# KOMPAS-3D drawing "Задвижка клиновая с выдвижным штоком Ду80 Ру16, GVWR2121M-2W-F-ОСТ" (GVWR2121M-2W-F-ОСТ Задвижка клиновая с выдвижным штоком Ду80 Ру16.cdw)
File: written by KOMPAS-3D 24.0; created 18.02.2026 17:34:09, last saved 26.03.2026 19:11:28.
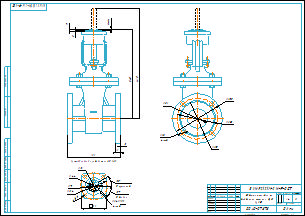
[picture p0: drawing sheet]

Document properties: Автор: R2D2; Форматы листов документа: A2; Полное имя файла: GVWR2121M-2W-F-ОСТ Задвижка клиновая с видвижным штоком Ду80 Ру16.cdw; Масса: 24; Наименование: Задвижка клиновая с выдвижным штоком Ду80 Ру16; Количество листов документа: 1; Примечание: D040-07878

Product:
- Part/product: Задвижка клиновая с выдвижным штоком Ду80 Ру16  | designation GVWR2121M-2W-F-ОСТ
    Масса: 24
    Раздел спецификации: Прочие изделия
    Форматы листов документа: A2
    Примечание: D040-07878

Views: Проекционный вид 2, Проекционный вид 3
Referenced files in E:\Работа\Зайцев\GVWR2121M-2W-F-ОСТ Задвижка клиновая с видвижным штоком Ду50-300 Ру16\DN80\: GVWR2121M-2W-F-ОСТ Задвижка клиновая с видвижным штоком Ду80 Ру16.m3d, GVWR2121M-2W-F-ОСТ Задвижка клиновая с выдвижным штоком Ду80 Ру16.m3d
Referenced files in E:\Работа\Зайцев\Для компаса\: чертеж DN.ru А3.cdt
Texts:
  GVWR2121M-2W-F-ОСТ
  Присоединение привода тип АК (А)
  чертеж DN.ru А3.cdt
  Задвижка клиновая с
  выдвижным штоком Ду80
  Ру16
  Задвижка клиновая с выдвижным штоком Ду80 Ру16
  GVWR2121M-2W-F-ОСТ Задвижка клиновая с выдвижным штоком Ду80 Ру16
Dimensions and other numbers on the sheet: 0; 3; 4; 195; 135; 80; 18; 4 отв.; 160; 100; 5 кулачков; 5 впадин; 14 (М12); 13,5; 104; 70; 44; 32; 1:2; 1; 2; 24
